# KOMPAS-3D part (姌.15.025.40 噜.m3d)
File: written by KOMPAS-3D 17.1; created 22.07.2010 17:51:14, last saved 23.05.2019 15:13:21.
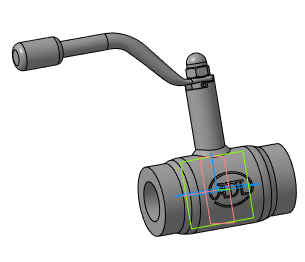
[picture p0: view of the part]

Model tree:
1. Плоскость XY
2. Плоскость ZX
3. Плоскость ZY
4. Ось X
5. Ось Y
6. Ось Z
7. Начало координат
8. Операция без истории:3  (labels: Сталь 20  ГОСТ 1050-88)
